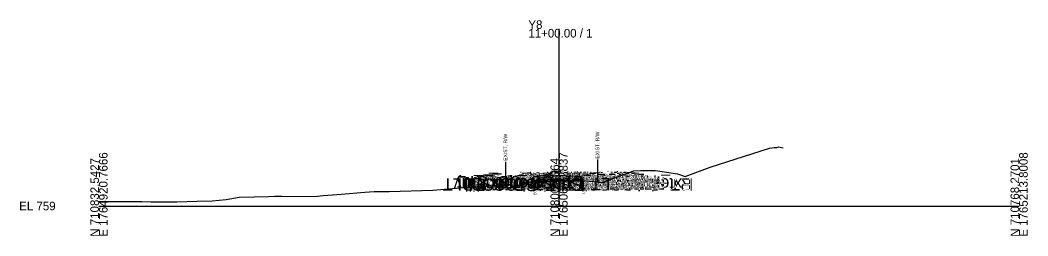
# Model space of a CAD drawing. Extents: x -26 to 1603, y -10 to 1060.
# Drawn here: x -25.7 to 302.8, y 990.3 to 1060.5 of the extents above; entities that cross this region are included whole.
import ezdxf

# ---------------------------------------------------------------- set-up
doc = ezdxf.new("R2010")
doc.units = 0
for name, color, linetype in [('Default', 7, 'Continuous'), ('Exist Cross Section Cell', 7, 'Continuous'), ('Exist XS Center Line Elevation Label', 7, 'Continuous'), ('Exist XS Ground Line', 7, 'Continuous'), ('Old_Level_10', 7, 'Continuous'), ('Prop CMT Pvmt Course 1', 7, 'Continuous'), ('Prop XS SE Text', 7, 'Continuous'), ('Scratch_Level_1', 7, 'Continuous'), ('Scratch_Level_7', 7, 'Continuous')]:
    doc.layers.add(name, color=color, linetype=linetype)

msp = doc.modelspace()

# ---------------------------------------------------------------- linework, layer by layer
at = {"layer": 'Exist Cross Section Cell'}
for p, q in [((150, 1000), (150, 1057.62)), ((0, 1000), (150, 1000)), ((150, 1000), (300, 1000))]:
    msp.add_line(p, q, dxfattribs=at)
at = {"layer": 'Exist XS Ground Line'}
msp.add_lwpolyline([(0, 1001.45), (3.89, 1001.47), (13.97, 1001.47), (16.91, 1001.38), (17.3, 1001.4), (17.92, 1001.36), (19.45, 1001.36), (20.05, 1001.36), (21.51, 1001.36), (23, 1001.36), (24.23, 1001.38), (25.4, 1001.4), (31.97, 1001.57), (36.91, 1001.74), (41.44, 1002.13), (45.73, 1002.87), (55.3, 1003.14), (57.33, 1003.21), (59.61, 1003.18), (70.24, 1003.14), (73.08, 1003.4), (76.17, 1003.68), (78.96, 1003.81), (86.66, 1004.5), (89.73, 1004.73), (91.83, 1004.72), (92.75, 1004.71), (94.65, 1004.73), (108.9, 1005.13), (120.4, 1006.08), (133.22, 1007.05), (135.28, 1006.77), (136.17, 1006.67), (136.52, 1006.77), (142.16, 1008.04), (146.42, 1008.19), (149.79, 1008.31), (154.56, 1008.28), (157.83, 1008.26), (161.77, 1007.87), (164.16, 1007.7), (171.35, 1010.4), (174.4, 1011.45), (176.51, 1011.52), (181.48, 1011.59), (188.59, 1010.48), (191.08, 1009.55), (199.3, 1012.65), (218.58, 1018.86), (220.14, 1019), (220.99, 1019.09), (221.52, 1019.21), (223.12, 1018.95)], dxfattribs=at)
at = {"layer": 'Old_Level_10'}
for p, q in [((132.5, 1014.4), (132.5, 1007)), ((162.51, 1015.12), (162.51, 1007.72)), ((142.16, 1008.04), (142.16, 1005.99)), ((157.83, 1008.26), (157.83, 1006.21))]:
    msp.add_line(p, q, dxfattribs=at)
at = {"layer": 'Prop CMT Pvmt Course 1'}
for points in [[(142.16, 1007.79), (150, 1008.06)], [(150, 1008.06), (150, 1008.31)], [(150, 1008.06), (150, 1008.06), (150, 1008.06)], [(157.83, 1008.01), (150, 1008.06)]]:
    msp.add_lwpolyline(points, dxfattribs=at)
at = {"layer": 'Scratch_Level_1'}
for p, q in [((142.16, 1008.04), (149.79, 1008.31)), ((149.79, 1008.31), (157.83, 1008.26))]:
    msp.add_line(p, q, dxfattribs=at)

# ---------------------------------------------------------------- texts
at = {"layer": 'Default'}
msp.add_text('-', height=0.0001, dxfattribs=at).set_placement((0, 1000))
at = {"layer": 'Exist Cross Section Cell'}
for s, p in [('Y8', (140, 1057.62)), ('11+00.00 / 1', (140, 1054.82)), ('EL 759', (-26, 998.6))]:
    msp.add_text(s, height=2.8, dxfattribs=at).set_placement(p)
for s, p in [('N 710832.5427', (0, 990)), ('E 1764920.7666', (2.8, 990)), ('N 710800.4064', (150, 990)), ('E 1765067.2837', (152.8, 990)), ('N 710768.2701', (300, 990)), ('E 1765213.8008', (302.8, 990))]:
    msp.add_text(s, height=2.8, rotation=90, dxfattribs=at).set_placement(p)
at = {"layer": 'Exist XS Center Line Elevation Label'}
msp.add_text('767.31', height=1, dxfattribs=at).set_placement((148.05, 1006.31))
at = {"layer": 'Old_Level_10'}
for s, height, p in [('EXIST. R/W', 1.181, (133.09, 1014.7)), ('EXIST. R/W', 1.181, (163.1, 1015.43)), ('EOP', 0.787, (142.55, 1003.6)), ('EOP', 0.787, (158.22, 1003.81))]:
    msp.add_text(s, height=height, rotation=90, dxfattribs=at).set_placement(p)
at = {"layer": 'Prop XS SE Text'}
for rotation, p in [(2.0045, (143.39, 1009.08)), (359.6562, (151.28, 1009.3))]:
    msp.add_text('EXIST.', height=1.5, rotation=rotation, dxfattribs=at).set_placement(p)
at = {"layer": 'Scratch_Level_1'}
for s, rotation, p in [('0.035', 1.995, (144.95, 1008.53)), ('0.006', 359.6518, (152.29, 1008.85))]:
    msp.add_text(s, height=1, rotation=rotation, dxfattribs=at).set_placement(p)
at = {"layer": 'Scratch_Level_7'}
for s, p in [('LT_Sub_OSS_DLT', (158.17, 1008.98)), ('Exterior Boundary', (158.47, 1008.85)), ('LT_Sub_Trench_Out', (166.67, 1009.1)), ('LT_GS_OS_CTL', (157.78, 1009.72)), ('LT_Slope_Fill', (151.97, 1008.85)), ('LT_PS3_Shelf_Out', (165.75, 1009.44)), ('LT_PV1_OEEOP', (161.86, 1009.79)), ('LT_PV2_OEEOP', (162.87, 1009.79)), ('LT_PV3_OEEOP', (162.9, 1009.45)), ('LT_Sub_OEEOP', (162.33, 1009.12)), ('LT_PV1_OEOT', (159.79, 1010.04)), ('LT_PS1_OEOP', (160.06, 1010.04)), ('LT_PS3_OEOP', (160.51, 1009.44)), ('LT_PS2_OEOP', (160.82, 1009.78)), ('LT_PV2_OEOT', (160.8, 1009.79)), ('LT_PV3_OEOT', (160.83, 1009.45)), ('LT_Sub_OEOT', (160.27, 1009.12)), ('RT_PV1_IEEOP', (169.32, 1010.06)), ('LT_PV1_IEEOP', (168.82, 1010.06)), ('RT_PV2_IEEOP', (170.33, 1010.06)), ('LT_PV2_IEEOP', (169.82, 1010.06)), ('RT_Sub_Trench_Out', (184.71, 1009.33)), ('RT_PV1_OEEOP', (178.03, 1010.01)), ('RT_PS3_Shelf_Out', (183.11, 1009.67)), ('PV1_PGL', (160.68, 1010.31)), ('RT_PV2_OEEOP', (179.04, 1010.01)), ('RT_PV3_OEEOP', (179.07, 1009.68)), ('RT_Sub_OEEOP', (178.5, 1009.35)), ('RT_PV1_OEOT', (175.97, 1010.26)), ('RT_PS1_OEOP', (176.24, 1010.26)), ('PV2_PGL', (161.68, 1010.06)), ('RT_PV2_OEOT', (176.98, 1010.01)), ('RT_PV3_OEOT', (177.01, 1009.68)), ('RT_Sub_OEOT', (176.44, 1009.35)), ('RT_PS2_OEOP', (177.5, 1010.01)), ('RT_PS3_OEOP', (177.87, 1009.67)), ('RT_GS_OS_CTL', (181.95, 1009.94)), ('RT_Sub_OSS_DLT', (193.35, 1009.04)), ('RT_Slope_Fill', (180.66, 1009.68)), ('Exterior Boundary', (193.67, 1009.04))]:
    msp.add_text(s, height=4, rotation=180, dxfattribs=at).set_placement(p)

doc.saveas('drawing.dxf')
